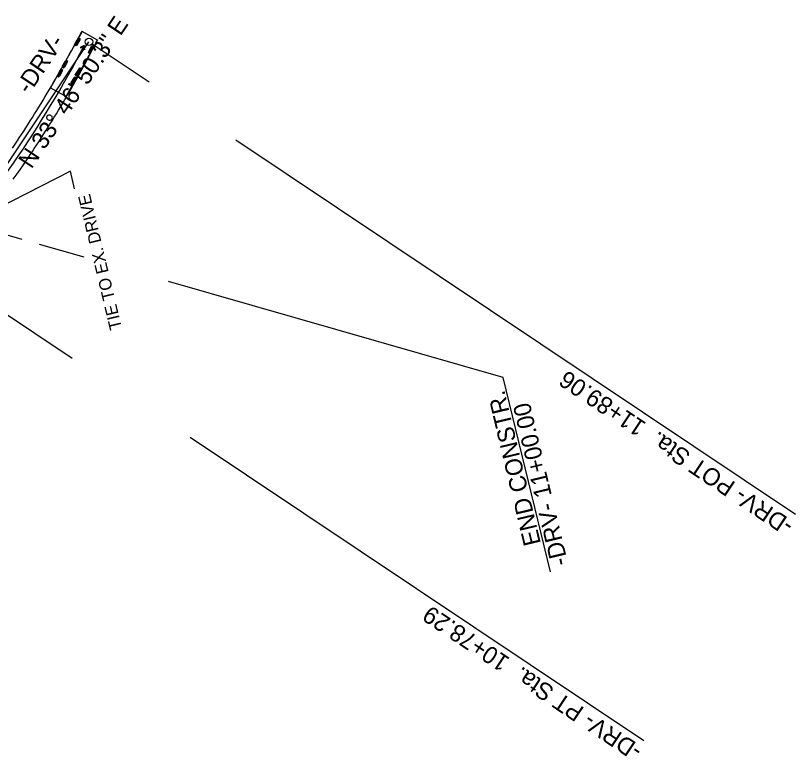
# Model space of a CAD drawing. Extents: x 1735795 to 1737428, y 699740 to 701024.
# Drawn here: x 1736351.1 to 1736668.3, y 700169.3 to 700470.7 of the extents above; entities that cross this region are included whole.
import ezdxf

# ---------------------------------------------------------------- set-up
doc = ezdxf.new("R2010")
doc.units = 0
for name, color, linetype in [('Prop Dimension', 7, 'Continuous'), ('Prop Dimension Text', 7, 'Continuous'), ('Prop Horizontal Alignment', 7, 'Continuous'), ('Prop Horizontal Alignment Direction Label', 7, 'Continuous'), ('Prop Horizontal Alignment Station Label', 7, 'Continuous'), ('Scratch_Level_4', 7, 'Continuous')]:
    doc.layers.add(name, color=color, linetype=linetype)

msp = doc.modelspace()

# ---------------------------------------------------------------- linework, layer by layer
at = {"layer": 'Prop Dimension'}
msp.add_lwpolyline([(1736375.15, 700400.17), (1736373.43, 700407.41), (1736331.46, 700386)], dxfattribs=at)
at = {"layer": 'Prop Horizontal Alignment'}
msp.add_line((1736319.39, 700367.96), (1736380.98, 700460.03), dxfattribs=at)
at = {"layer": 'Prop Horizontal Alignment Station Label'}
for p, q in [((1736382.23, 700459.19), (1736405.44, 700443.67)), ((1736440.64, 700420.12), (1736668.26, 700267.86)), ((1736320.64, 700367.13), (1736374.15, 700331.33)), ((1736422.19, 700299.2), (1736606.67, 700175.79))]:
    msp.add_line(p, q, dxfattribs=at)
for points in [[(1736353.77, 700379.6), (1736331.46, 700386)], [(1736378.97, 700372.37), (1736360.88, 700377.56)], [(1736568.63, 700244.43), (1736549.43, 700323.47), (1736413.34, 700362.51)]]:
    msp.add_lwpolyline(points, dxfattribs=at)
msp.add_circle((1736380.98, 700460.03), 1.5, dxfattribs=at)
at = {"layer": 'Scratch_Level_4'}
for p, q in [((1736378.15, 700464.21), (1736365.38, 700441.28)), ((1736384.4, 700460.73), (1736378.15, 700464.21)), ((1736378.15, 700464.21), (1736378.15, 700464.21)), ((1736371.63, 700437.8), (1736384.4, 700460.73)), ((1736376.85, 700461.56), (1736375.32, 700458.6)), ((1736377.04, 700461.46), (1736375.5, 700458.5)), ((1736377.22, 700461.36), (1736375.69, 700458.41)), ((1736382.39, 700458.5), (1736380.85, 700455.55)), ((1736382.57, 700458.41), (1736381.03, 700455.45)), ((1736382.76, 700458.31), (1736381.22, 700455.35)), ((1736370.22, 700449.54), (1736371.84, 700452.45)), ((1736370.4, 700449.43), (1736372.02, 700452.35)), ((1736370.58, 700449.33), (1736372.2, 700452.25)), ((1736368.19, 700445.9), (1736369.81, 700448.81)), ((1736368.37, 700445.79), (1736369.99, 700448.71)), ((1736368.55, 700445.69), (1736370.18, 700448.61)), ((1736375.74, 700446.46), (1736377.36, 700449.38)), ((1736375.92, 700446.36), (1736377.54, 700449.27)), ((1736376.1, 700446.26), (1736377.72, 700449.17)), ((1736373.71, 700442.82), (1736375.33, 700445.73)), ((1736373.89, 700442.72), (1736375.51, 700445.63)), ((1736374.08, 700442.62), (1736375.7, 700445.53)), ((1736365.38, 700441.28), (1736371.63, 700437.8))]:
    msp.add_line(p, q, dxfattribs=at)
for points in [[(1736351.9, 700419.82), (1736352.63, 700420.92), (1736353.54, 700422.3), (1736354.44, 700423.69), (1736355.34, 700425.08), (1736356.23, 700426.47), (1736357.12, 700427.86), (1736358, 700429.26), (1736358.88, 700430.66), (1736359.75, 700432.07), (1736360.61, 700433.48), (1736361.47, 700434.89), (1736362.33, 700436.31), (1736363.18, 700437.72), (1736364.02, 700439.15), (1736364.86, 700440.57), (1736365.69, 700442), (1736366.52, 700443.43), (1736367.35, 700444.86), (1736368.16, 700446.3), (1736368.98, 700447.74), (1736369.78, 700449.18), (1736370.59, 700450.63), (1736371.39, 700452.07), (1736372.19, 700453.52), (1736373, 700454.96), (1736373.8, 700456.41), (1736374.61, 700457.85), (1736375.41, 700459.3), (1736376.22, 700460.74), (1736377.02, 700462.19), (1736377.82, 700463.63), (1736378.15, 700464.21)], [(1736357.98, 700415.44), (1736358.72, 700416.56), (1736359.65, 700417.96), (1736360.56, 700419.37), (1736361.48, 700420.78), (1736362.39, 700422.2), (1736363.29, 700423.62), (1736364.19, 700425.04), (1736365.08, 700426.46), (1736365.96, 700427.89), (1736366.85, 700429.33), (1736367.72, 700430.76), (1736368.59, 700432.2), (1736369.46, 700433.64), (1736370.32, 700435.09), (1736371.17, 700436.53), (1736372.02, 700437.99), (1736372.86, 700439.44), (1736373.7, 700440.9), (1736374.53, 700442.36), (1736375.36, 700443.82), (1736376.18, 700445.29), (1736377, 700446.76), (1736377.81, 700448.24), (1736378.61, 700449.71), (1736379.41, 700451.19), (1736380.21, 700452.67), (1736380.99, 700454.16), (1736381.78, 700455.65), (1736382.55, 700457.14), (1736383.32, 700458.63), (1736384.09, 700460.13), (1736384.4, 700460.73)], [(1736349.88, 700416.79), (1736351.72, 700419.54), (1736351.9, 700419.82)], [(1736350.17, 700404.07), (1736352.11, 700406.82), (1736354.02, 700409.59), (1736355.92, 700412.36), (1736357.79, 700415.16), (1736357.98, 700415.44)]]:
    msp.add_lwpolyline(points, dxfattribs=at)
for points in [[(1736376.81, 700461.58), (1736377.27, 700461.34), (1736377.19, 700460.85), (1736376.09, 700458.73), (1736375.73, 700458.38), (1736375.27, 700458.62), (1736375.35, 700459.11), (1736376.45, 700461.24)], [(1736379.04, 700458.46), (1736377.42, 700457.7), (1736378.62, 700457.66), (1736379.35, 700456.7)], [(1736382.34, 700458.53), (1736382.8, 700458.29), (1736382.73, 700457.8), (1736381.62, 700455.67), (1736381.26, 700455.33), (1736380.8, 700455.57), (1736380.88, 700456.06), (1736381.99, 700458.19)], [(1736370.63, 700449.31), (1736370.17, 700449.56), (1736370.26, 700450.05), (1736371.43, 700452.14), (1736371.79, 700452.47), (1736372.25, 700452.22), (1736372.16, 700451.74), (1736370.99, 700449.64)], [(1736368.6, 700445.67), (1736368.14, 700445.92), (1736368.24, 700446.4), (1736369.4, 700448.5), (1736369.77, 700448.83), (1736370.22, 700448.58), (1736370.13, 700448.1), (1736368.96, 700446)], [(1736376.15, 700446.23), (1736375.69, 700446.49), (1736375.78, 700446.97), (1736376.95, 700449.07), (1736377.31, 700449.4), (1736377.77, 700449.15), (1736377.68, 700448.66), (1736376.51, 700446.57)], [(1736374.12, 700442.59), (1736373.67, 700442.85), (1736373.76, 700443.33), (1736374.92, 700445.43), (1736375.29, 700445.76), (1736375.74, 700445.51), (1736375.65, 700445.02), (1736374.48, 700442.93)]]:
    msp.add_lwpolyline(points, close=True, dxfattribs=at)
for centre in [(1736378.15, 700464.21), (1736384.4, 700460.73), (1736379.04, 700458.46), (1736351.9, 700419.82), (1736351.9, 700419.82), (1736357.98, 700415.44), (1736357.98, 700415.44)]:
    msp.add_circle(centre, 0.0417, dxfattribs=at)
msp.add_arc((1735985.33, 700663.12), 443.73, 318.1062, 332.5324, dxfattribs=at)

# ---------------------------------------------------------------- texts
at = {"layer": 'Prop Dimension Text'}
msp.add_text('TIE TO EX. DRIVE', height=5, rotation=103.4184, dxfattribs=at).set_placement((1736394.44, 700343.52))
at = {"layer": 'Prop Horizontal Alignment Direction Label'}
for s, p in [('N 33%%d 46\' 50.3" E', (1736357.6, 700408.02)), ('-DRV-', (1736356.64, 700438.4))]:
    msp.add_text(s, height=7, rotation=56.2194, dxfattribs=at).set_placement(p)
at = {"layer": 'Prop Horizontal Alignment Station Label'}
for s, rotation, p in [('-DRV- POT Sta.  11+89.06', 146.2194, (1736668.09, 700264.58)), ('END CONSTR.', 103.4184, (1736564.8, 700255.93)), ('-DRV- 11+00.00', 103.4184, (1736575.89, 700247.65)), ('-DRV- PT Sta.  10+78.29', 146.2194, (1736606.55, 700172.94))]:
    msp.add_text(s, height=7, rotation=rotation, dxfattribs=at).set_placement(p)

doc.saveas('drawing.dxf')
